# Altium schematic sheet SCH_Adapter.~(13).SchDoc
size A
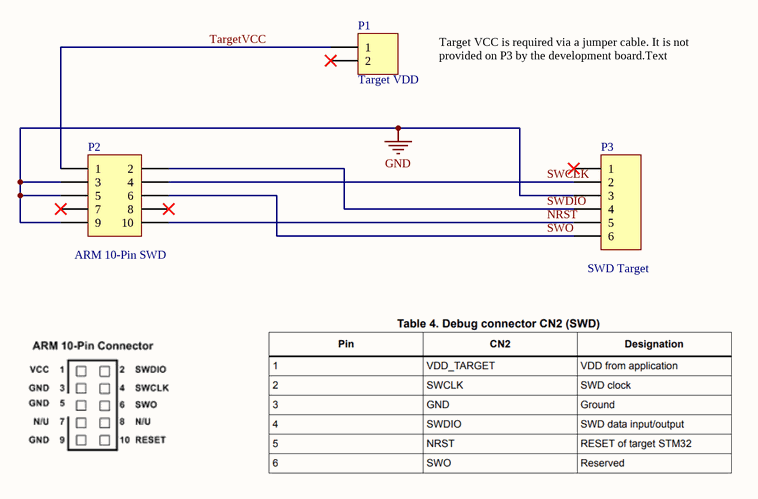
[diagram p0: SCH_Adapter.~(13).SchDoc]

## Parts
P1  Target VDD  [HDR1X2]
P2  ARM 10-Pin SWD  [HDR2X5]
P3  SWD Target  [HDR1X6]

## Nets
GND: P2.3 P2.5 P2.9 P3.3
NRST: P2.10 P3.5
SWCLK: P2.4 P3.2
SWDIO: P2.2 P3.4
SWO: P2.6 P3.6
TargetVCC: P1.1 P2.1

Not connected (* = marked no-connect by the designer): P1 2*; P2 7* 8*; P3 1*

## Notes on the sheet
- Target VCC is required via a jumper cable. It is not provided on P3 by the development board.Text

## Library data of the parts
P1 = Header 2: Header, 2-Pin
P2 = Header 5X2: Header, 5-Pin, Dual row
P3 = Header 6: Header, 6-Pin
